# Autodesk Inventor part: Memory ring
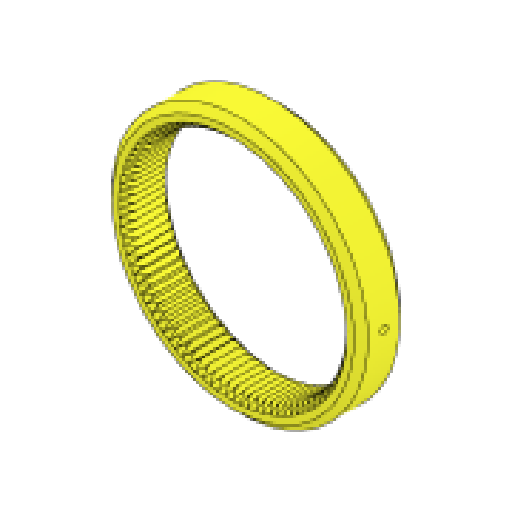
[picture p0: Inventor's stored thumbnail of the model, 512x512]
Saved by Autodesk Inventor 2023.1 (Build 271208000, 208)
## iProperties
Created: 2020-02
Part Number: Memory ring
Material: Generic
Document SubType Name: Modeling
Designer: ftrauzettel
Density: 1 g/cm^3
Appearance: Default
Sending System: SolidWorks 2016
Last Author: Pam
Last Saved: 2020-10-15
Author: ftrauzettel
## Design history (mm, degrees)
fillet "Fillet5"
body "Solid1"
